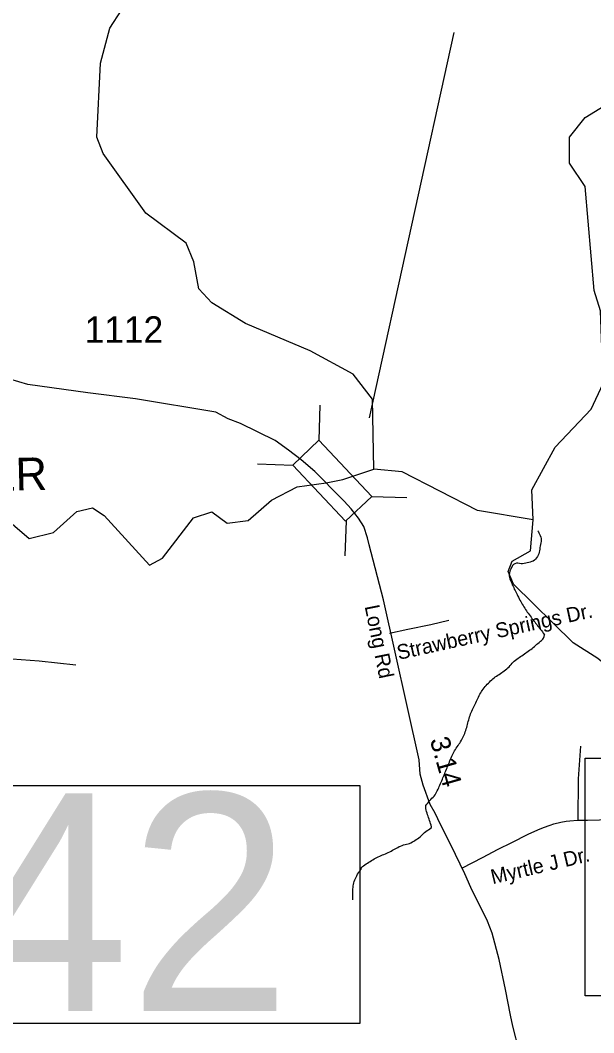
# Model space of a CAD drawing. Extents: x 1950930 to 2061844, y 904556 to 1017002.
# Drawn here: x 1978977 to 1982667, y 922665 to 929175 of the extents above; entities that cross this region are included whole.
import ezdxf

# ---------------------------------------------------------------- set-up
doc = ezdxf.new("R2010")
doc.units = 0
for name, color, linetype in [('Exist Hydrographic Creek Single Shore', 7, 'Continuous'), ('Exist Hydrographic Misc Water Feature', 7, 'Continuous'), ('Exist Hydrographic River Shore Label', 7, 'Continuous'), ('Exist Road Non-System Type 51', 7, 'Continuous'), ('Exist Road Non-System Type 51 Label', 7, 'Continuous'), ('Exist Road Primary US Structure Standard Bridge CELL', 7, 'Continuous'), ('Exist Road Secondary Mileage Hundredths English Label', 7, 'Continuous'), ('Exist Road Secondary Structure Standard Bridge CELL', 7, 'Continuous'), ('Exist Road Secondary Structure Standard Bridge Number Label', 7, 'Continuous'), ('Exist Road Secondary Type 41 Attributed', 7, 'Continuous'), ('Exist Road Secondary Type 51 Attributed', 7, 'Continuous'), ('Exist Road Secondary Type 51 Label', 7, 'Continuous'), ('Exist Road Secondary Type 51 Number Label', 7, 'Continuous')]:
    doc.layers.add(name, color=color, linetype=linetype)

msp = doc.modelspace()

# ---------------------------------------------------------------- linework, layer by layer
at = {"layer": 'Exist Hydrographic Creek Single Shore'}
for points in [[(1981250.8, 926288.9), (1981242.8, 926738.7), (1981117.9, 926898.8), (1980842.8, 927048.8), (1980426.9, 927224.8), (1980209.8, 927357.3), (1980126.9, 927447.7), (1980092.9, 927622.3), (1980043.9, 927741.4), (1979784.9, 927933.8), (1979510.7, 928316.9), (1979468.9, 928422.8), (1979493.9, 928898.2), (1979552.8, 929123.4), (1979702.9, 929356.6)], [(1977583.8, 926065.8), (1977650.9, 926041.5), (1978158.8, 925709.3), (1978274.9, 925723.4), (1978491.8, 925965.1), (1978616.9, 926031.4), (1978850.9, 926000.3), (1979033.8, 925842.3), (1979191.9, 925881.7), (1979341.8, 926016.4), (1979441.8, 926040.6), (1979516.9, 925989.9), (1979808.9, 925672.1), (1979891.9, 925716.4), (1980091.9, 925974.7), (1980208.9, 926015), (1980308.8, 925940.7), (1980442.9, 925957.7), (1980592.8, 926089.2), (1980758.9, 926174.4), (1980945.9, 926199.9), (1981053.1, 926222), (1981250.8, 926288.9)], [(1982275.9, 925962.6), (1981917.9, 926022.4), (1981433.9, 926272), (1981250.8, 926288.9)], [(1984366, 923513.8), (1984074, 923588.8), (1983923.9, 923713.2), (1983791, 923896.5), (1983482.9, 924162.1), (1983474.9, 924428.1), (1983417, 924554), (1983224.9, 924722.1), (1982891.9, 924906.2), (1982692, 925071.2), (1982533.9, 925172.8), (1982150.8, 925548.3), (1982117, 925631), (1982142, 925696.2), (1982258.9, 925762.6), (1982275.9, 925962.6)]]:
    msp.add_lwpolyline(points, dxfattribs=at)
at = {"layer": 'Exist Hydrographic Misc Water Feature'}
for points in [[(1982275.9, 925962.6), (1982267.9, 926156.3), (1982418, 926428.9), (1982650.9, 926673.5), (1982726.8, 926839.4), (1982710, 927305.7), (1982669, 927437.9), (1982610.9, 928105.3), (1982510.9, 928255.1), (1982510.9, 928422.4), (1982610.9, 928548.4), (1982827.9, 928681.7), (1982902.9, 928781.9), (1983011.8, 929314.7)], [(1982307.6, 925892), (1982309.2, 925888.9), (1982313.7, 925879.7), (1982318, 925870.5), (1982322.6, 925861.3), (1982326, 925852.2), (1982328.9, 925843.3), (1982329.3, 925833.4), (1982327.7, 925823.6), (1982325.2, 925813.8), (1982323, 925803.2), (1982321.7, 925793.2), (1982320.7, 925783.7), (1982319.5, 925773.8), (1982317.2, 925763.9), (1982315.2, 925754.1), (1982312.7, 925744.2), (1982309, 925735.1), (1982304.7, 925726.4), (1982298.6, 925717.6), (1982292.2, 925709.7), (1982285, 925703), (1982277.2, 925697.3), (1982267.8, 925694.3), (1982258, 925691.3), (1982247.9, 925688.8), (1982238.1, 925686.6), (1982228.6, 925683.6), (1982219, 925681.4), (1982209, 925680.2), (1982198.9, 925680.1), (1982188.7, 925682.8), (1982179, 925683.8), (1982169.2, 925683.3), (1982158.9, 925680.1), (1982149.9, 925675.2), (1982144.2, 925668.1), (1982138.8, 925659.1), (1982133.9, 925650.5), (1982130.2, 925640.6), (1982126.5, 925631.8), (1982124.1, 925622), (1982122.4, 925611.3), (1982122.8, 925601.5), (1982124.7, 925592.3), (1982127.4, 925582.5), (1982130.8, 925573.1), (1982134.3, 925563.2), (1982138.8, 925554.5), (1982142.7, 925545.3), (1982147.2, 925536.1), (1982151.5, 925526.9), (1982155.6, 925517.8), (1982160, 925508.6), (1982165.1, 925500.1), (1982169, 925491.4), (1982173.9, 925482.1), (1982178.4, 925472.9), (1982182.9, 925465), (1982187.8, 925455.6), (1982192.1, 925446.5), (1982197.1, 925438), (1982202, 925429.2), (1982206.9, 925420.7), (1982211.8, 925411.8), (1982217, 925403.3), (1982222.3, 925395.2), (1982227.6, 925386.7), (1982233.2, 925378.5), (1982238.9, 925369.9), (1982244.8, 925361.8), (1982250.6, 925353.6), (1982256.5, 925345.8), (1982262.9, 925337.5), (1982268.6, 925329.3), (1982274.8, 925321.9), (1982280.9, 925313.2), (1982286.9, 925305.8), (1982292.8, 925297.6), (1982299.6, 925290.1), (1982305.3, 925281.5), (1982311.3, 925274.2), (1982317.8, 925266.7), (1982324, 925258.4), (1982329.5, 925250.7), (1982335.9, 925242.4), (1982342, 925234.2), (1982350.4, 925223.1)], [(1982141.1, 925040.7), (1982148.3, 925047.7), (1982155.6, 925054.3), (1982163.6, 925060.4), (1982171.6, 925066), (1982179.6, 925072.6), (1982187.8, 925078.2), (1982195.8, 925083.9), (1982204, 925089.2), (1982212.2, 925095.5), (1982220.4, 925101.3), (1982228.6, 925106.9), (1982236.8, 925112.6), (1982245.1, 925118.6), (1982253.3, 925124.7), (1982261.5, 925129.9), (1982269.7, 925135.6), (1982277.4, 925142.1), (1982285.2, 925148.2), (1982292.8, 925154.8), (1982300.4, 925162.2), (1982307.8, 925168.3), (1982315.2, 925174.9), (1982323.2, 925181.5), (1982331, 925187.5), (1982338.1, 925195), (1982343.9, 925202.2), (1982347.4, 925211.8), (1982350.4, 925223.1)], [(1981650.6, 924203.4), (1981655.9, 924211.9), (1981660.2, 924220.9), (1981664.8, 924230), (1981669.3, 924238.6), (1981673, 924247.9), (1981677.3, 924256.9), (1981681.6, 924266.4), (1981685.1, 924275.6), (1981688.7, 924284.4), (1981692.8, 924294.3), (1981696.5, 924303.1), (1981700.6, 924312.3), (1981704.3, 924321.8), (1981708, 924331), (1981711.7, 924340.5), (1981715.4, 924349.8), (1981719.1, 924359.3), (1981722.6, 924368.1), (1981726.3, 924377.3), (1981730, 924386.9), (1981733.7, 924396), (1981737.8, 924405.5), (1981741.4, 924414.8), (1981745.5, 924423.5), (1981749.6, 924433.4), (1981753.7, 924442.2), (1981757.8, 924451.3), (1981761.7, 924460.4), (1981766.7, 924469), (1981771.6, 924477.9), (1981776.7, 924486.1), (1981782.2, 924494.1), (1981788, 924503.1), (1981793.7, 924511.2), (1981799.3, 924519.3), (1981804.8, 924527.2), (1981810.1, 924536.2), (1981815.1, 924545.2), (1981820, 924554.2), (1981823.9, 924562.9), (1981828.4, 924571.9), (1981832.5, 924581.1), (1981836.6, 924589.8), (1981839.9, 924599.5), (1981843.1, 924608.8), (1981846.4, 924618.4), (1981849.3, 924628), (1981851.8, 924637.9), (1981854.4, 924646.8), (1981857.1, 924656.9), (1981859.6, 924666.7), (1981862, 924676.4), (1981864.5, 924686.3), (1981867.3, 924695.9), (1981870.6, 924704.8), (1981873.9, 924714.9), (1981877.6, 924723.6), (1981881.7, 924733.1), (1981885.8, 924742.2), (1981890.3, 924751.3), (1981894.6, 924760.4), (1981899.1, 924769), (1981903.2, 924778.1), (1981907.1, 924786.8), (1981911.8, 924796.7), (1981915.9, 924805.8), (1981920.2, 924814.5), (1981924.8, 924823.5), (1981929.3, 924832.7), (1981934.2, 924841.3), (1981939.3, 924849.4), (1981944.2, 924858.4), (1981949.8, 924866.4), (1981955.7, 924874.5), (1981962.3, 924882.8), (1981968.6, 924890), (1981975, 924897.9), (1981981.8, 924905.4), (1981988.5, 924912.5), (1981995.1, 924919.6), (1982002.3, 924927), (1982009.9, 924933.3), (1982017.6, 924939.7), (1982025, 924946.3), (1982033.4, 924952.3), (1982041.4, 924958.1), (1982049.6, 924963.7), (1982058.2, 924969.2), (1982066.5, 924974.9), (1982074.7, 924980.6), (1982082.7, 924985.8), (1982091.1, 924992.3), (1982099.3, 924997.9), (1982107.1, 925004.5), (1982114.4, 925010.7), (1982121.6, 925018), (1982128, 925025.2), (1982134.3, 925033.2), (1982141.1, 925040.7)], [(1981115.8, 923519.2), (1981116.2, 923529.4), (1981116.2, 923539.1), (1981116.6, 923548.7), (1981116.6, 923559.7), (1981117.5, 923569.3), (1981117.3, 923579.1), (1981117.3, 923589.2), (1981118.1, 923598.9), (1981119.3, 923608.8), (1981121.4, 923618.7), (1981123.8, 923628), (1981126.3, 923638.1), (1981130.2, 923647.8), (1981133.3, 923656.6), (1981137.8, 923665.6), (1981142.3, 923674.7), (1981147.2, 923683.8), (1981152.5, 923692.7), (1981158.1, 923700.7), (1981164, 923708.8), (1981170.4, 923716.7), (1981171.6, 923726.6), (1981178, 923733), (1981186, 923738.7), (1981194.6, 923744.3), (1981203.2, 923749.9), (1981211.8, 923755), (1981219.4, 923760.8), (1981228, 923766.4), (1981236.2, 923772), (1981245.2, 923777.6), (1981253.6, 923782.4), (1981262.4, 923787.1), (1981271.7, 923791), (1981280.5, 923795.7), (1981289.7, 923799.6), (1981298.7, 923803.5), (1981308.2, 923808.2), (1981317.2, 923811.3), (1981326.2, 923815.2), (1981335.9, 923819), (1981344.7, 923824.1), (1981353.9, 923827.6), (1981362.3, 923832.4), (1981371.3, 923838), (1981379.7, 923842.8), (1981388.5, 923847.5), (1981397.4, 923852.2), (1981406.4, 923856.9), (1981415.2, 923861.8), (1981424.2, 923865.5), (1981433.5, 923869.4), (1981442.9, 923872.9), (1981452.7, 923875.1), (1981462.4, 923877.2), (1981472, 923879.4), (1981481.8, 923882.4), (1981490.7, 923886.4), (1981500.1, 923891.4), (1981508.1, 923896.7), (1981516.5, 923901.5), (1981525.1, 923907.1), (1981533.7, 923912.7), (1981541.9, 923918.3), (1981549.3, 923924.9), (1981556.9, 923931.9), (1981563.5, 923938.1), (1981570.6, 923945.6), (1981578.2, 923953), (1981586, 923959), (1981594.2, 923964.8), (1981602.8, 923970.3), (1981612.3, 923975.9), (1981620.1, 923981.5), (1981622.7, 923989.7), (1981620.5, 923999.8), (1981616.6, 924009.7), (1981613.5, 924019.4), (1981610.6, 924029.3), (1981607.7, 924038.2), (1981604.3, 924048), (1981601.2, 924057.5), (1981597.7, 924066.5), (1981594.2, 924076.3), (1981591.6, 924086.5), (1981589.3, 924096.1), (1981587.2, 924105.9), (1981586.2, 924115.7), (1981587.4, 924125.7), (1981592.4, 924133.9), (1981599.1, 924141.7), (1981605.7, 924150.2), (1981612.3, 924157.2), (1981619, 924164.3), (1981625.6, 924172.6), (1981632.6, 924179.7), (1981638.9, 924186.9), (1981645.5, 924195.2), (1981650.6, 924203.4)]]:
    msp.add_lwpolyline(points, dxfattribs=at)
at = {"layer": 'Exist Road Non-System Type 51'}
for points in [[(1981352.5, 925233.2), (1981471.5, 925259.1), (1981619.1, 925290.6), (1981733.6, 925316.7)], [(1982565.8, 924031.5), (1982568, 924297.8), (1982582.4, 924507.7)], [(1981821.2, 923724.4), (1981950.1, 923791.6), (1982052, 923844.2), (1982139.5, 923888.4), (1982243.9, 923941.1), (1982306.8, 923969.1), (1982342.4, 923984.4), (1982386.5, 924000.5), (1982409.5, 924007.2), (1982455.8, 924018.8), (1982488.9, 924024.7), (1982512.6, 924028.1), (1982561, 924031.5), (1982565.8, 924031.5)], [(1982565.8, 924031.5), (1982626.4, 924031.5), (1982704.5, 924034), (1982823, 924039.6), (1982884.1, 924043.8), (1982924, 924046.3), (1982978.4, 924048.9), (1983007, 924049.4)]]:
    msp.add_lwpolyline(points, dxfattribs=at)
at = {"layer": 'Exist Road Secondary Mileage Hundredths English Label'}
msp.add_lwpolyline([(1982611.3, 924430.7), (1985187.8, 924430.7), (1985187.8, 922901.5), (1982611.3, 922901.5)], close=True, dxfattribs=at)
at = {"layer": 'Exist Road Secondary Structure Standard Bridge CELL'}
for p, q in [((1980905.5, 926700.1), (1980898.7, 926473.9)), ((1980503.8, 926322), (1980730.1, 926315.1)), ((1981237.7, 926112.1), (1981463.9, 926105.3)), ((1981072.9, 925957), (1981066, 925730.7))]:
    msp.add_line(p, q, dxfattribs=at)
msp.add_lwpolyline([(1980898.7, 926473.9), (1981238.5, 926112.9), (1981069.8, 925954.1), (1980730.1, 926315.1)], close=True, dxfattribs=at)
at = {"layer": 'Exist Road Secondary Structure Standard Bridge Number Label'}
msp.add_line((1981224.5, 926618.1), (1981769.1, 929096), dxfattribs=at)
msp.add_lwpolyline([(1978585.8, 924253.9), (1981162.4, 924253.9), (1981162.4, 922724.6), (1978585.8, 922724.6)], close=True, dxfattribs=at)
at = {"layer": 'Exist Road Secondary Type 41 Attributed'}
msp.add_lwpolyline([(1978925.1, 925067.9), (1979099, 925055.8), (1979334.7, 925029.6)], dxfattribs=at)
at = {"layer": 'Exist Road Secondary Type 51 Attributed'}
for points in [[(1980945.9, 926199.9), (1980873.3, 926274.1), (1980785, 926348.3), (1980702.9, 926411.5), (1980617.7, 926471.7), (1980394.5, 926582.6), (1980315.5, 926613), (1980235.1, 926654), (1979718.1, 926741.4), (1979412.2, 926778.6), (1979026.5, 926833.3), (1978791.9, 926900.9)], [(1982187.7, 922548.2), (1982146, 922707), (1982130.8, 922778.4), (1982099.7, 922943.3), (1982058.7, 923136.3), (1982013.9, 923305.7), (1981982, 923381.7), (1981875.7, 923599), (1981837.8, 923685.6), (1981747.5, 923873.5), (1981681.5, 924003.4), (1981647.4, 924077.4), (1981613.3, 924133.2), (1981569.6, 924257.6), (1981550.9, 924327.2), (1981543.4, 924420.2), (1981314, 925447.7), (1981222.7, 925802.3), (1981212.1, 925847.9), (1981187.8, 925920.8), (1981152.9, 925972.5), (1981105.8, 926033.3), (1981060.3, 926083.4), (1980971.1, 926173.1), (1980945.9, 926199.9)]]:
    msp.add_lwpolyline(points, dxfattribs=at)

# ---------------------------------------------------------------- texts
at = {"layer": 'Exist Hydrographic River Shore Label'}
msp.add_text('RIVER', height=210, rotation=1.47625, dxfattribs=at).set_placement((1978294.1, 926133.8))
at = {"layer": 'Exist Road Non-System Type 51 Label'}
for s, rotation, p in [('Strawberry Springs Dr.', 12.3513, (1981411.4, 925061.9)), ('Myrtle J Dr.', 13.35218, (1982016.3, 923619.1))]:
    msp.add_text(s, height=95, rotation=rotation, dxfattribs=at).set_placement(p)
at = {"layer": 'Exist Road Primary US Structure Standard Bridge CELL'}
msp.add_text('3.14', height=125, rotation=285.79899, dxfattribs=at).set_placement((1981611.3, 924547.9))
at = {"layer": 'Exist Road Secondary Structure Standard Bridge Number Label'}
msp.add_text('42', height=1400, dxfattribs=at).set_placement((1978636, 922803.7))
at = {"layer": 'Exist Road Secondary Type 51 Label'}
msp.add_text('Long Rd', height=95, rotation=281.48821, dxfattribs=at).set_placement((1981192.4, 925406.4))
at = {"layer": 'Exist Road Secondary Type 51 Number Label'}
msp.add_text('1112', height=170, dxfattribs=at).set_placement((1979391.2, 927101))

doc.saveas('drawing.dxf')
